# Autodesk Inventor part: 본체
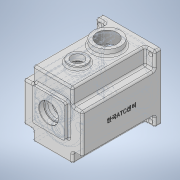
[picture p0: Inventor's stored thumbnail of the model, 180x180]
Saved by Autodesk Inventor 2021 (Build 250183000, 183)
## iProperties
Created: 2022-08
Part Number: 본체
Material: 일반
Document SubType Name: Modeling
Designer: Owner
Density: 2.7 g/cm^3
Appearance: 기본값
Mass: 1404.2 g
Surface Area: 1170.75 cm^2
Volume: 520.076 cm^3
Author: Owner
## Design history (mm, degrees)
sketch "스케치2"
  geometry: L1 (-55, 49)-(55, 49); L2 (55, 49)-(55, -49); L3 (55, -49)-(-55, -49); L4 (-55, -49)-(-55, 49); L5 (-55, 49)-(55, -49); L6 (55, 49)-(-55, -49); 1 further point
  constraints: 12 end point, 2 midpoint, 2 parallel, 1 horizontal, 1 perpendicular
  dimensions: "d0" = 110 distance between parallel lines of L4 L2; "d1" = 98 distance between parallel lines of L3 L1
extrude "돌출1" new body sketch "스케치2" distance "d2" = 130; taper "d3" = 0 deg
sketch "스케치3"
  geometry: L1 (33, 55)-(49, 55); L2 (49, 55)-(49, 28); L3 (49, 28)-(33, 28); L4 (33, 28)-(33, 55); L5 (49, 55)-(-49, 55) reference; L6 (49, -55)-(49, 55) reference; 1 further point
  constraints: 8 end point, 2 parallel, 1 horizontal, 1 perpendicular
  dimensions: "d4" = 27 distance between parallel lines of L3 L1; "d5" = 16 distance between parallel lines of L2 L4; "d6" = 0 distance between parallel lines of L5 L1; "d7" = 0 distance between parallel lines of L6 L2
extrude "돌출2" cut sketch "스케치3" distance "d8" = 120; taper "d9" = 0 deg
node "작업 평면1"
sketch "스케치4"
  geometry: L1 (33, -38)-(49, -38); L2 (49, -38)-(49, -55); L3 (49, -55)-(33, -55); L4 (33, -55)-(33, -38); L5 (-49, -55)-(49, -55) reference; L6 (49, -55)-(49, 28) reference; 1 further point
  constraints: 8 end point, 2 parallel, 1 horizontal, 1 perpendicular
  dimensions: "d11" = 17 distance between parallel lines of L1 L3; "d12" = 16 distance between parallel lines of L2 L4; "d13" = 0 distance between parallel lines of L5 L3; "d14" = 0 distance between parallel lines of L6 L2
extrude "돌출3" cut sketch "스케치4" distance "d15" = 120; taper "d16" = 0 deg
sketch "스케치5"
  geometry: L1 (-23, 45)-(23, 45); L2 (23, 45)-(23, 33.249); L3 (-23, 33.249)-(-23, 45); L4 (-49, -55)-(49, -55) reference; A1 r 42 centre (0, -5) between (-25.375, 28.468) and (25.375, 28.468); A2 r 6 centre (-29, 33.249) between (-25.375, 28.468) and (-23, 33.249); A3 r 6 centre (29, 33.249) between (23, 33.249) and (25.375, 28.468); 5 further points
  constraints: 8 point on circle, 6 end point, 4 tangent, 3 centre point, 2 point on line, 1 horizontal, 1 parallel, 1 perpendicular, 1 vertical alignment
  dimensions: "d18" = 84 diameter of A1; "d19" = 50 distance from line of L4 A1.centre; "d20" = 50 distance from line of A1.centre L1; "d21" = 46 distance between parallel lines of L2 L3; "d22" = 23 distance from line of point (0, 0) L2; "d28" = 6 radius of A2; "d29" = 6 radius of A3
extrude "돌출4" cut sketch "스케치5" distance "d23" = 121; taper "d24" = 0 deg
sketch "스케치7"
  geometry: L1 (23, 45)-(23, 33.249) reference; L2 (-23, 45)-(23, 45) reference; L3 (-23, 33.249)-(-23, 45) reference; L4 (26, 48)-(26, 33.249); L5 (-26, 33.249)-(-26, 48); L6 (-26, 48)-(26, 48); A1 r 6 centre (29, 33.249) between (23, 33.249) and (25.375, 28.468) reference; A2 r 6 centre (-29, 33.249) between (-25.375, 28.468) and (-23, 33.249) reference; A3 r 42 centre (0, -5) between (-25.375, 28.468) and (25.375, 28.468) reference; A4 r 3 centre (29, 33.249) between (26, 33.249) and (27.188, 30.859); A5 r 45 centre (0, -5) between (-27.188, 30.859) and (27.188, 30.859); A6 r 3 centre (-29, 33.249) between (-27.188, 30.859) and (-26, 33.249); 1 further point
  constraints: 6 end point, 6 point on circle, 3 centre point, 5 other
  dimensions: "d30" = 3 distance between parallel lines of L2 L6
extrude "돌출6" cut sketch "스케치7" distance "d31" = 9; taper "d32" = 0 deg
sketch "스케치8"
  geometry: L1 (0, 98)-(0, 0) reference; C1 r 22.5 at (-40, 49); 2 further points
  constraints: 1 centre point, 1 horizontal alignment, 1 midpoint
  dimensions: "d33" = 40 distance from line of L1 C1.centre; "d34" = 45 diameter of C1
extrude "돌출7" join sketch "스케치8" distance "d35" = 10; taper "d36" = 0 deg
sketch "스케치9"
  geometry: C1 r 22.5 at (0, 0) reference; 2 further points
  constraints: 1 coincident
hole "구멍1" sketch "스케치9" at (0, 0) diameter "d37" = 33.376; stored, may be unused: countersink angle "d41" = 90 deg, drill point angle "d43" = 118 deg; dims "d38" = 70, "d39" = 4, "d40" = 2, "d42" = 77.3
sketch "스케치10"
  geometry: L1 (0, 98)-(0, 0) reference; C1 r 15 at (-89, 49); 2 further points
  constraints: 1 centre point, 1 horizontal alignment, 1 midpoint
  dimensions: "d44" = 30 diameter of C1; "d45" = 89 distance from line of L1 C1.centre
extrude "돌출8" join sketch "스케치10" distance "d46" = 5; taper "d47" = 0 deg
sketch "스케치11"
  geometry: C1 r 15 at (0, 0) reference; C2 r 15 at (0, 0) reference; C3 r 10 at (0, 0); 1 further point
  constraints: 1 centre point, 1 coincident
  dimensions: "d48" = 20 diameter of C3
extrude "돌출9" cut sketch "스케치11" distance "d49" = 37.5; taper "d50" = 0 deg
sketch "스케치12"
  geometry: C1 r 10 at (32, 23) reference; C2 r 15 at (32, 23); 1 further point
  constraints: 1 centre point, 1 coincident
  dimensions: "d51" = 30 diameter of C2
extrude "돌출10" cut sketch "스케치12" distance "d52" = 5; taper "d53" = 0 deg
sketch "스케치13"
  geometry: L1 (-27, -21)-(27, -21); L2 (27, -21)-(27, 33); L3 (27, 33)-(-27, 33); L4 (-27, 33)-(-27, -21); L5 (-27, -21)-(27, 33); L6 (27, -21)-(-27, 33); L7 (49, 28)-(33, 28) reference; L8 (-33, -55)-(33, -55) reference; 3 further points
  constraints: 12 end point, 3 midpoint, 2 parallel, 1 horizontal, 1 perpendicular, 1 vertical alignment
  dimensions: "d54" = 54 distance between parallel lines of L2 L4; "d55" = 54 distance between parallel lines of L3 L1; "d73" = 88 distance between parallel lines of L3 L8
extrude "돌출11" join sketch "스케치13" distance "d56" = 7; taper "d57" = 0 deg
sketch "스케치23" dims "d83" = 8
  geometry: L1 (-71.164, -5)-(75.838, -5); L2 (-49, -55)-(49, -55) reference; L3 (-35.778, -1.006)-(-41.81, -1.006); L4 (-35.778, -8.994)-(-41.81, -8.994); A1 r 36 centre (0, -5) between (-36, -5) and (-35.778, -1.006); A2 r 42 centre (0, -5) between (-25.375, 28.468) and (25.375, 28.468) reference; 3 further points
  constraints: 6 end point, 3 point on circle, 2 horizontal, 2 symmetric about line, 1 centre point, 1 point on line, 1 vertical alignment, 3 other
  dimensions: "d82" = 50 distance between parallel lines of L2 L1; "d84" = 72 diameter of A1; "d85" = 50 distance from line of L2 A1.centre
extrude "돌출12" join sketch "스케치23" stored distance "d86" = 7; taper "d87" = 0 deg
sketch "스케치26"
  geometry: L1 (33, -55)-(-33, -55) reference; C1 r 21 at (0, 6); C2 r 15 at (0, -25); 3 further points
  constraints: 2 centre point, 2 vertical alignment
  dimensions: "d88" = 42 diameter of C1; "d89" = 61 distance from line of L1 C1.centre; "d90" = 31 distance of C1.centre C2.centre; "d91" = 30 diameter of C2
extrude "돌출13" join sketch "스케치26" distance "d92" = 7; taper "d93" = 0 deg
sketch "스케치27"
  geometry: C1 r 11 at (0, -25); A1 r 15 centre (0, -25) between (-8.978, -12.984) and (8.978, -12.984) reference; 1 further point
  constraints: 1 centre point, 1 coincident
  dimensions: "d94" = 22 diameter of C1
extrude "돌출14" cut sketch "스케치27" distance "d95" = 7; taper "d96" = 0 deg
sketch "스케치28"
  geometry: C1 r 11 at (0, 0) reference; C2 r 9.5 at (0, 0); 1 further point
  constraints: 1 centre point, 1 coincident
  dimensions: "d97" = 19 diameter of C2
extrude "돌출15" cut sketch "스케치28" distance "d98" = 3; taper "d99" = 0 deg
sketch "스케치29"
  geometry: C1 r 17.5 at (0, 6); A1 r 21 centre (0, 6) between (8.978, -12.984) and (-8.978, -12.984) reference; 1 further point
  constraints: 1 centre point, 1 coincident
  dimensions: "d100" = 35 diameter of C1
extrude "돌출16" cut sketch "스케치29" distance "d101" = 10; taper "d102" = 0 deg
sketch "스케치30"
  geometry: C1 r 17.5 at (0, 0) reference; C2 r 14 at (0, 0); 1 further point
  constraints: 1 centre point, 1 coincident
  dimensions: "d103" = 28 diameter of C2
extrude "돌출17" cut sketch "스케치30" stored distance "d104" = 10; taper "d105" = 0 deg
sketch "스케치31"
  geometry: C1 r 14 at (0, 6) reference; C2 r 16 at (0, 6); A1 r 21 centre (0, 6) between (8.978, -12.984) and (-8.978, -12.984) reference; 1 further point
  constraints: 1 centre point, 1 coincident
  dimensions: "d106" = 32 diameter of C2
extrude "돌출18" cut sketch "스케치31" distance "d107" = 8.3; taper "d108" = 0 deg
sketch "스케치32"
  geometry: L1 (-49, 55)-(-49, -55) reference; L2 (49, 55)-(-49, 55) reference; C1 r 3.5 at (-42, 48); 1 further point
  constraints: 1 centre point
  dimensions: "d109" = 7 diameter of C1; "d110" = 7 distance from line of L1 C1.centre; "d111" = 7 distance from line of L2 C1.centre
extrude "돌출19" cut sketch "스케치32" stored distance "d112" = 8.3; taper "d113" = 0 deg
sketch "스케치33"
  geometry: A1 r 4 centre (-36, -5) between (-35.778, -8.994) and (-35.778, -1.006) reference; 2 further points
  constraints: 1 coincident
hole "구멍2" sketch "스케치33" at (-36, -5) diameter "d120" = 3.242; stored, may be unused: countersink angle "d124" = 90 deg, drill point angle "d126" = 118 deg; dims "d121" = 7, "d122" = 4, "d123" = 2, "d125" = 9
sketch "스케치34"
  geometry: A1 r 4 centre (36, -5) between (35.778, -1.006) and (35.778, -8.994) reference; 2 further points
  constraints: 1 coincident
hole "구멍3" sketch "스케치34" at (36, -5) diameter "d127" = 3.242; stored, may be unused: countersink angle "d131" = 90 deg, drill point angle "d133" = 118 deg; dims "d128" = 7, "d129" = 4, "d130" = 2, "d132" = 9
sketch "스케치35"
  geometry: L1 (-130, 17)-(-130, 83) reference; L2 (-130, 110)-(-10, 110) reference; 2 further points
  constraints: 1 other
  dimensions: "d134" = 65 distance from line of L1 point (-65, 50); "d135" = 60 distance from line of L2 point (-65, 50)
feature "엠보싱1" sketch "스케치35" dims "d136" = 0.5, "d137" = 0
fillet "모깎기1" dims "d141" = 3
fillet "모깎기3" dims "d143" = 6
chamfer "모따기2" distance "d144" = 1; stored, may be unused: second distance "d145" = 2, angle "d146" = 45 deg
fillet "모깎기5" dims "d148" = 3
fillet "모깎기6" dims "d149" = 3
fillet "모깎기7" dims "d150" = 3
fillet "모깎기8" dims "d151" = 3
fillet "모깎기9" dims "d152" = 0.3
fillet "모깎기10" dims "d153" = 0.3
fillet "모깎기11" dims "d154" = 0.3
chamfer "모따기3" distance "d155" = 0.8; stored, may be unused: second distance "d156" = 2, angle "d157" = 30 deg
chamfer "모따기4" distance "d158" = 1; stored, may be unused: second distance "d159" = 2, angle "d160" = 30 deg
fillet "모깎기15" dims "d164" = 3
fillet "모깎기18" dims "d167" = 3
fillet "모깎기19" dims "d168" = 3
fillet "모깎기20" dims "d169" = 3
fillet "모깎기21" dims "d170" = 3
fillet "모깎기22" dims "d171" = 3
fillet "모깎기23" dims "d172" = 3
fillet "모깎기24" dims "d173" = 3
fillet "모깎기25" dims "d174" = 3
fillet "모깎기26" dims "d175" = 3
fillet "모깎기27" dims "d176" = 3
fillet "모깎기28" dims "d177" = 3
fillet "모깎기29" dims "d178" = 3
fillet "모깎기30" dims "d179" = 3
fillet "모깎기31" dims "d180" = 3
fillet "모깎기32" dims "d181" = 3
fillet "모깎기33" dims "d182" = 3
chamfer "모따기5" distance "d183" = 1; stored, may be unused: second distance "d184" = 2, angle "d185" = 30 deg
fillet "모깎기34" dims "d186" = 3
fillet "모깎기35" dims "d187" = 3
node "솔리드1"
mirror "미러1"
mirror "미러2"
mirror "미러3"
pattern_linear "직사각형 패턴1" dims "d116" = 84, "d119" = 96
node "투영된 루프2"
node "투영된 루프3"
feature "A9D066F2-1C7D-4E18-AEED-F7BC21143FA4" dims "d37" = 33.376, "d38" = 70, "d39" = 4, "d40" = 2, "d41" = 90 deg, "d42" = 77.3, "d43" = 118 deg
other parameters: "d10" = -49
